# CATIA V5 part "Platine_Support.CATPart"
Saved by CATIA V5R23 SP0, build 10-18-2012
Part number: Platine_Support
Material "Aluminium": density 2710 kg/m3, Young's modulus 7e+10 Pa, Poisson ratio 0.346, thermal expansion 2.36e-05 1/K
Bounding box of the stored display mesh (mm): x 0 to 15, y -45 to 45, z 0 to 227.5
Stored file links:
  P:\CORRECTION CAO\Platine_Support.CATPart
  C:\Program Files\Dassault Systemes\B23\win_b64\startup\materials\French\Catalog.CATMaterial
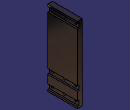
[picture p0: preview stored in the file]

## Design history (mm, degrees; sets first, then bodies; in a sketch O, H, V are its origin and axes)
Body1 (main body)
  Sketch1 on xy-plane, origin (0, 0, 0), H (1, 0, 0), V (0, 1, 0)
    line L1 (0, -45) -> (15, -45)
    line L2 (15, -45) -> (15, 45)
    line L3 (15, 45) -> (0, 45)
    line L4 (0, 45) -> (0, -45)
    reference intersected line E2 through (0, 0) direction (-1, 0) from zx-plane
    reference intersected line E3 through (0, 0) direction (0, 1) from yz-plane
    distance L1 L3 = 90
    distance L2 L4 = 15
    horizontal: L1 H, L3 H
    vertical: L2 V, L4 V
    symmetry: L3 L1 E2
    coincidence: E3 L4
  Pad1: profile Sketch1, direction (0, 0, 1), length 227.5
  Sketch2 on zx-plane, origin (0, 0, 0), H (-1, 0, 0), V (0, 0, 1)
    line L1 (-33, 222.2) -> (-10, 222.2)
    line L2 (-10, 222.2) -> (-10, 207.2)
    line L3 (-10, 207.2) -> (-33, 207.2)
    line L4 (-33, 207.2) -> (-33, 222.2)
    line L5 (-33, 60) -> (-10, 60)
    line L6 (-10, 60) -> (-10, 45)
    line L7 (-10, 45) -> (-33, 45)
    line L8 (-33, 45) -> (-33, 60)
    point P7 (-10, 45)
    reference intersected line E1 (-15, 0) -> (-15, 227.5) from face of Pad1
    line L9 (-33, 5) -> (-10, 5)
    line L10 (-10, 5) -> (-10, 20)
    line L11 (-10, 20) -> (-33, 20)
    line L12 (-33, 20) -> (-33, 5)
    point P11 (-10, 20)
    reference intersected line E2 through (0, 0) direction (-1, 0) from xy-plane
    reference projected line E3 (-15, 0) -> (-15, 227.5) from edge [face of Pad1 from Sketch1.L3 | face of Pad1 from Sketch1.L2]
    distance L3 L1 = 15
    distance L7 L5 = 15 {= Sketch2.distance(L3 L1)}
    distance L2 E1 = 5
    distance L3 L5 = 147.2
    distance L9 L11 = 15 {= Sketch2.distance(L3 L1)}
    distance E2 L9 = 5
    distance L4 E3 = 18
    distance L7 L11 = 25
    horizontal: L1 H, L3 H, L5 H, L7 H, L9 H, L11 H
    vertical: L2 V, L4 V, L6 V, L8 V, L10 V, L12 V
    coincidence: P7 L2, P11 L2, L4 L8, L8 L12
  Pocket1: profile Sketch2, direction (0, -1, 0), through (limit type 3), opposite side through (limit type 3)
  Sketch3 on face of Pad1, origin (0, 21.7871, 73.1335), H (0, 1, 0), V (0, 0, -1)
    point P1 (13.2129, 20.6335)
    reference intersected line E1 through (-21.7871, 0) direction (0, 1) from zx-plane
    reference intersected line E4 through (0, 28.1335) direction (-1, 0) from face of Pocket1
    reference intersected line E5 through (0, 13.1335) direction (-1, 0) from face of Pocket1
    distance P1 E1 = 35
    equidistance: E4 E5 P1
  Hole1: placed by Sketch3, at (0, 35, 52.5) direction (1, 0, 0), diameter 5.5, through (limit type 6), counterbore diameter 9, counterbore depth 6
  Mirror1: of Hole1, about zx-plane
  Sketch4 "Esquisse.4" on face of Pad1, origin (0, 29.4563, 237.7937), H (0, 1, 0), V (0, 0, -1)
    point P1 (5.5437, 23.0937)
    reference intersected line E1 through (-29.4563, 0) direction (0, 1) from zx-plane
    reference intersected line E2 through (0, 30.5937) direction (-1, 0) from face of Pocket1
    reference intersected line E3 through (0, 15.5937) direction (-1, 0) from face of Pocket1
    distance P1 E1 = 35
    equidistance: E2 E3 P1
  Hole2 "Trou.2": placed by Sketch4, at (0, 35, 214.7) direction (1, 0, 0), diameter 5.5, through (limit type 6), counterbore diameter 9, counterbore depth 6
  Mirror2: of Hole2, about zx-plane
  Sketch5 "Esquisse.5" on face of Pad1, origin (0, 33.8713, 11.5014), H (0, 1, 0), V (0, 0, -1)
    point P1 (1.1287, -0.9986)
    reference intersected line E1 through (-33.8713, 0) direction (0, 1) from zx-plane
    reference intersected line E2 through (0, -8.4986) direction (-1, 0) from face of Pocket1
    reference intersected line E3 through (0, 6.5014) direction (-1, 0) from face of Pocket1
    distance P1 E1 = 35
    equidistance: E2 E3 P1
  Hole3 "Trou.3": placed by Sketch5, at (0, 35, 12.5) direction (1, 0, 0), diameter 5.5, through (limit type 6), counterbore diameter 9, counterbore depth 6
  Mirror3: of Hole3, about zx-plane
  Sketch6 "Esquisse.6" on face of Pocket1, origin (10, -1.3345, 13.0241), H (0, 1, 0), V (0, 0, 1)
    point P1 (1.3345, -0.5241)
    reference intersected line E1 through (1.3345, 0) direction (0, 1) from zx-plane
    reference intersected line E2 (-43.6655, 6.9759) -> (46.3345, 6.9759) from face of Pocket1
    reference intersected line E3 (46.3345, -8.0241) -> (-43.6655, -8.0241) from face of Pocket1
    coincidence: P1 E1
    equidistance: E2 E3 P1
  Hole4 "Trou.4": placed by Sketch6, at (10, 0, 12.5) direction (-1, 0, 0), diameter 6, depth 6, V-bottom angle 120
  Sketch7 "Esquisse.7" on face of Pocket1, origin (10, 9.8233, 74.3702), H (0, 1, 0), V (0, 0, 1)
    point P1 (-9.8233, -21.8702)
    reference intersected line E1 (-54.8233, -14.3702) -> (35.1767, -14.3702) from face of Pocket1
    reference intersected line E2 (35.1767, -29.3702) -> (-54.8233, -29.3702) from face of Pocket1
    reference intersected line E3 through (-9.8233, 0) direction (0, 1) from zx-plane
    equidistance: E1 E2 P1
    coincidence: P1 E3
  Hole5 "Trou.5": placed by Sketch7, at (10, 0, 52.5) direction (-1, 0, 0), diameter 6, depth 6, V-bottom angle 120
  Sketch8 "Esquisse.8" on face of Pocket1, origin (10, 3.6684, 236.9932), H (0, 1, 0), V (0, 0, 1)
    point P1 (-3.6684, -22.2932)
    reference intersected line E1 (41.3316, -29.7932) -> (-48.6684, -29.7932) from face of Pocket1
    reference intersected line E2 (-48.6684, -14.7932) -> (41.3316, -14.7932) from face of Pocket1
    reference intersected line E3 through (-3.6684, 0) direction (0, 1) from zx-plane
    equidistance: E1 E2 P1
    coincidence: P1 E3
  Hole6 "Trou.6": placed by Sketch8, at (10, 0, 214.7) direction (-1, 0, 0), diameter 6, depth 6, V-bottom angle 120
